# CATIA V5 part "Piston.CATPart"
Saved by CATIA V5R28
Part number: Piston
Bounding box of the stored display mesh (mm): x -10.5 to 10.5, y -10.5 to 10.499, z 0 to 20
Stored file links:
  D:\Back up\Mission d'enseignement\TP Catia\2 oct - Assemblage\Piston.CATPart
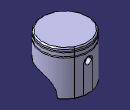
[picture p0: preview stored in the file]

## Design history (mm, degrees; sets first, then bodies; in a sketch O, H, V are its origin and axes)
Body1 (main body)
  Sketch1 on yz-plane, origin (0, 0, 0), H (0, 1, 0), V (0, 0, 1)
    axis line L1 (0, 67.0846) -> (0, -65.3024)
    point P1 (0, 67.0846)
    point P3 (0, 20)
    line L2 (0, 20) -> (10.5, 20)
    point P4 (10.5, 20)
    line L3 (10.5, 20) -> (10.5, 18.75)
    point P5 (10.5, 0)
    line L4 (10.5, 0) -> (8.5, 0)
    line L5 (8.5, 0) -> (8.5, 17)
    line L6 (8.5, 17) -> (0, 17)
    point P8 (0, 17)
    line L7 (0, 17) -> (0, 20)
    arc A1 centre (10.5, 18.5) radius 0.25 from (10.5, 18.75) to (10.5, 18.25) ccw
    point P9 (10.5, 18.5)
    arc A2 centre (10.5, 16.5) radius 0.25 from (10.5, 16.75) to (10.5, 16.25) ccw
    point P10 (10.5, 16.5)
    point P11 (10.5, 18.25)
    line L8 (10.5, 18.25) -> (10.5, 16.75)
    line L9 (10.5, 16.25) -> (10.5, 0)
    length L2 = 10.5
    length L4 = 2
    distance L2 L6 = 3
    radius A1 = 0.25
    distance P9 L2 = 1.5
    distance P9 P10 = 2
    distance P4 P5 = 20
    coincidence: P1 V, P3 L1, P8 L1, L4 H, P9 L3, P10 L3, L3 P11, L3 L8, L8 L9
    vertical: L1 V, L3 V, L5 V, L7 V, L8 V, L9 V
    horizontal: L2 H, L4 H, L6 H
    equal size: A2 A1
  Shaft1: profile Sketch1, axis Sketch1.L1, angle 360
  Sketch2 on xy-plane, origin (0, 0, 0), H (1, 0, 0), V (0, 1, 0)
    point P1 (0, 11.2504)
    line L1 (2, 12.193) -> (2, 10.3078)
    line L2 (2, 10.3078) -> (-2, 10.3078)
    line L3 (-2, 10.3078) -> (-2, 12.193)
    line L4 (-2, 12.193) -> (2, 12.193)
    point P3 (2, 10.3078)
    reference projected circle E1 centre (0, 0) radius 10.5 from edge [face of Shaft1 from Sketch1.L2 | face of Shaft1 from Sketch1.L3]
    length L4 = 4
    coincidence: P1 V, P3 E1
    vertical: L1 V, L3 V
    horizontal: L2 H, L4 H
    equidistance: L1 L3 P1, L2 L4 P1
  Pocket1: profile Sketch2, direction (0, 0, 1), length 13
  Sketch3 on face of Pocket1 from Sketch2.L2, origin (0, 10.3078, 0), H (-1, 0, 0), V (0, 0, 1)
    circle A1 centre (0, 13) radius 2
    point P1 (0, 13)
    reference projected line E1 (-2, 13) -> (2, 13) from edge [end face of Pocket1 | face of Pocket1 from Sketch2.L2]
    radius A1 = 2
    coincidence: P1 E1
  Pocket2: profile Sketch3, direction (0, 1, 0), through (limit type 6)
  Sketch4 on face of Pocket2, origin (0, 10.3078, 0), H (-1, 0, 0), V (0, 0, 1)
    circle A1 centre (0, 13) radius 1.5
    point P1 (0, 13)
    reference projected arc E1 centre (0, 13) radius 2 from (2, 13) to (-2, 13) ccw from edge [start face of Pocket2 | face of Pocket2 from Sketch3.A1]
    radius A1 = 1.5
    coincidence: P1 V
    concentricity: A1 E1
  Pocket3: profile Sketch4, direction (0, -1, 0), through (limit type 3)
  Sketch5 on yz-plane, origin (0, 0, 0), H (0, 1, 0), V (0, 0, 1)
    reference intersected line E2 (-10.5, 0) -> (-10.5, 11.5) from face of Shaft1 from Sketch1.L9
    point P7 (5.5, 0)
    line L1 (5.5, 0) -> (-10.5, 0)
    line L2 (-10.5, 0) -> (-10.5, 9)
    line L3 (-10.5, 9) -> (-2.5, 9)
    line L4 (5.5, 1) -> (5.5, 0)
    point P9 (-10.5, 9)
    arc A1 centre (-2.5, 1) radius 8 from (5.5, 1) to (-2.5, 9) ccw
    radius A1 = 8
    distance L4 L2 = 16
    distance L1 L3 = 9
    coincidence: P7 H, P9 E2
    horizontal: L1 H, L3 H
    vertical: L2 V, L4 V
    tangency: A1 L4, A1 L3
  Pocket4: profile Sketch5, direction (-1, 0, 0), through (limit type 3), opposite side through (limit type 3)
  Sketch6 on zx-plane, origin (0, 0, 0), H (-1, 0, 0), V (0, 0, 1)
    arc A1 centre (0, -3.1244) radius 14 from (7, 9) to (-7, 9) ccw
    point P1 (0, -3.1244)
    point P2 (7, 9)
    point P3 (-7, 9)
    reference projected line E1 through (0, 0) direction (0, -1) from axis of face of Shaft1 from Sketch1.L5
    reference projected line E2 through (0, 0) direction (0, -1) from axis of face of Shaft1 from Sketch1.L9
    reference projected line E3 (-10.198, 9) -> (10.198, 9) from edge [face of Shaft1 from Sketch1.L9 | face of Pocket4 from Sketch5.L3]
    line L1 (-7, 9) -> (7, 9)
    point P4 (-7, 9)
    point P5 (7, 9)
    distance P3 E1 = 7
    distance P2 E2 = 7
    radius A1 = 14
    coincidence: P1 V, P3 E3, P4 A1, P5 P2, P4 P3
  Pocket5: profile Sketch6, direction (0, -1, 0), through (limit type 3)
  Chamfer1: length 0.5, angle 45, on edge [face of Shaft1 from Sketch1.L2 | face of Shaft1 from Sketch1.L3]; edge [face of Shaft1 from Sketch1.L9 | face of Shaft1 from Sketch1.L4]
